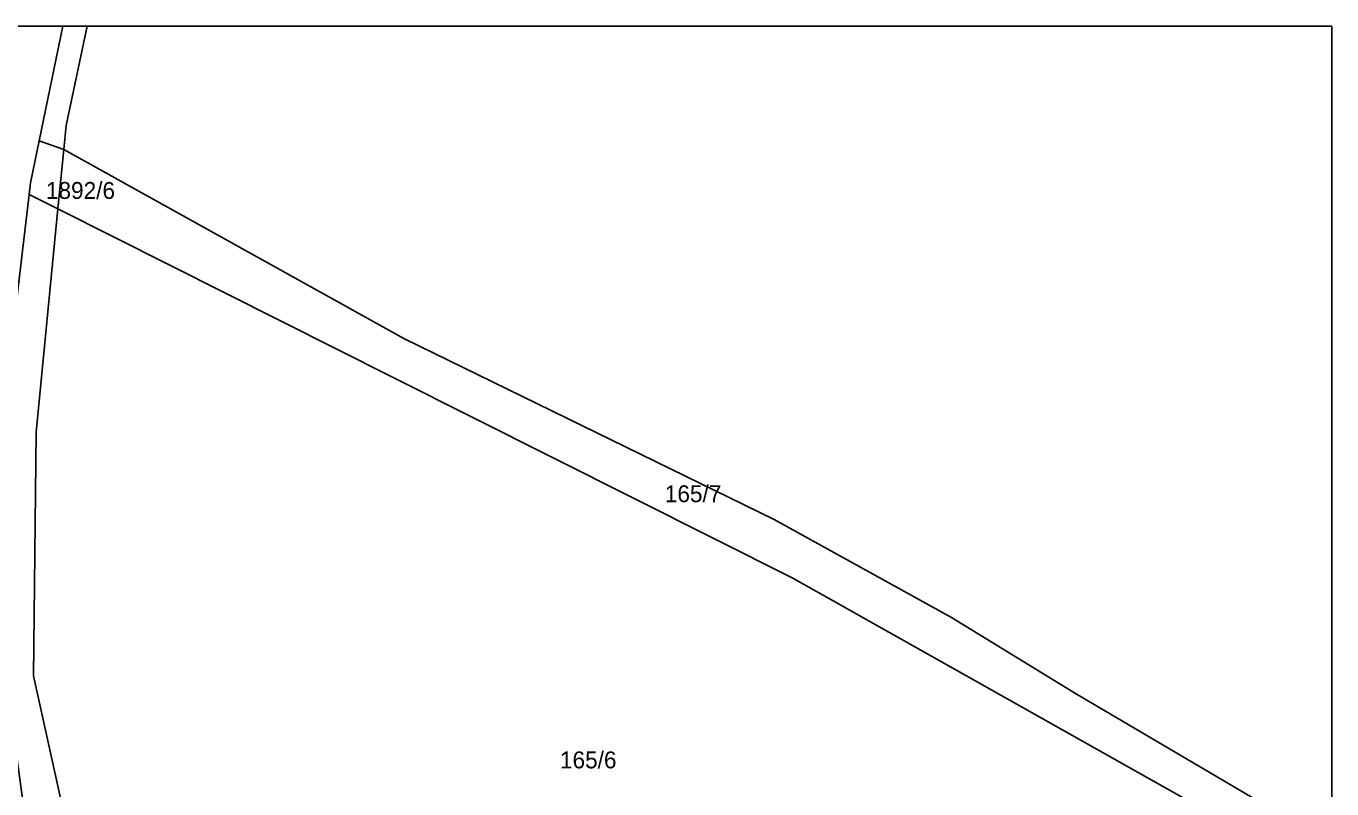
# Model space of a CAD drawing. Extents: x -559956 to -559707, y -1077221 to -1076919.
# Drawn here: x -559822.9 to -559707, y -1076986.4 to -1076918.8 of the extents above; entities that cross this region are included whole.
import ezdxf

# ---------------------------------------------------------------- set-up
doc = ezdxf.new("R2010")
doc.units = 0
doc.layers.add('Parcela-polygon', color=7, linetype='Continuous')
doc.layers.add('Parcela-text', color=7, linetype='Continuous')

msp = doc.modelspace()

# ---------------------------------------------------------------- linework, layer by layer
at = {"layer": 'Parcela-polygon'}
for p, q in [((-559819.59, -1076918.77), (-559829.56, -1076918.77)), ((-559817.45, -1076918.77), (-559819.59, -1076918.77)), ((-559707.02, -1076918.77), (-559817.45, -1076918.77)), ((-559707.02, -1076987.64), (-559707.02, -1076918.77))]:
    msp.add_line(p, q, dxfattribs=at)
for points in [[(-559823.69, -1076942.95), (-559822.57, -1076933.71), (-559822.47, -1076932.66), (-559821.7, -1076928.96), (-559819.59, -1076918.77)], [(-559819.59, -1076918.77), (-559821.7, -1076928.96), (-559819.52, -1076929.72), (-559819.31, -1076927.58), (-559817.45, -1076918.77)], [(-559817.45, -1076918.77), (-559819.31, -1076927.58), (-559819.52, -1076929.72), (-559789.34, -1076946.47), (-559756.49, -1076962.53), (-559740.76, -1076971.23), (-559729.78, -1076977.96), (-559713.09, -1076987.78), (-559709.61, -1076989.7), (-559708.48, -1076988.95), (-559707.02, -1076987.64)]]:
    msp.add_lwpolyline(points, dxfattribs=at)
for points in [[(-559821.7, -1076928.96), (-559822.47, -1076932.66), (-559822.57, -1076933.71), (-559820.03, -1076934.98), (-559819.52, -1076929.72)], [(-559820.03, -1076934.98), (-559790.36, -1076949.92), (-559754.85, -1076967.72), (-559750.31, -1076970.28), (-559712.43, -1076991.58), (-559709.61, -1076989.7), (-559713.09, -1076987.78), (-559729.78, -1076977.96), (-559740.76, -1076971.23), (-559756.49, -1076962.53), (-559789.34, -1076946.47), (-559819.52, -1076929.72)], [(-559824.5, -1076951.91), (-559824.93, -1076960.91), (-559824.89, -1076969.92), (-559824.18, -1076979.89), (-559822.96, -1076988.81), (-559821.27, -1076998.68), (-559820.21, -1077004.57), (-559819.43, -1077009.52), (-559817.92, -1077019.93), (-559817.45, -1077021.39), (-559816.36, -1077023.11), (-559814.85, -1077024.48), (-559813.27, -1077025.59), (-559813.57, -1077021.42), (-559815.76, -1077006.35), (-559818.24, -1076994.33), (-559822.2, -1076976.41), (-559821.95, -1076954.78), (-559820.03, -1076934.98), (-559822.57, -1076933.71), (-559823.69, -1076942.95)], [(-559790.36, -1076949.92), (-559820.03, -1076934.98), (-559821.95, -1076954.78), (-559822.2, -1076976.41), (-559818.24, -1076994.33), (-559800.74, -1076999.68), (-559769.74, -1077009.16), (-559751.72, -1077017.71), (-559712.43, -1076991.58), (-559750.31, -1076970.28), (-559754.85, -1076967.72)]]:
    msp.add_lwpolyline(points, close=True, dxfattribs=at)

# ---------------------------------------------------------------- texts
at = {"layer": 'Parcela-text'}
for s, p in [('1892/6', (-559821.1, -1076934.1)), ('165/7', (-559766.2, -1076961)), ('165/6', (-559775.5, -1076984.6))]:
    msp.add_text(s, height=1.5, dxfattribs=at).set_placement(p)

doc.saveas('drawing.dxf')
